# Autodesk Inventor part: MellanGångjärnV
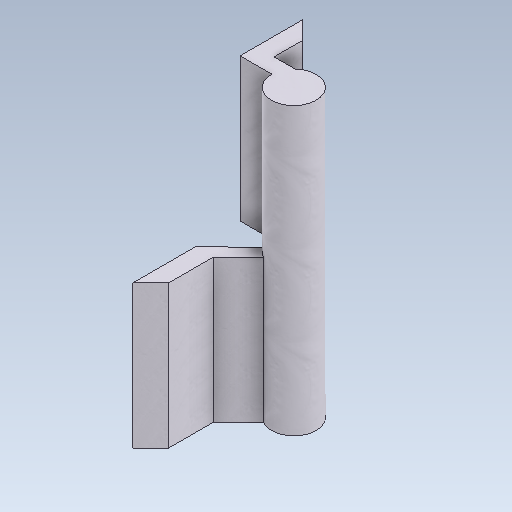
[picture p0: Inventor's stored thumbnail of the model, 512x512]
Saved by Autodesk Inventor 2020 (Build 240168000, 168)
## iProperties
Created: 2019-06
Part Number: MellanGångjärnV
Material: Aluminum 6061, Welded
Document SubType Name: Modeling
Designer: cl
Density: 2.7 g/cm^3
Appearance: Weld - Aluminum
Author: cl
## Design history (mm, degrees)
sketch "Sketch1"
  geometry: L1 (0, 0)-(0, -35); L2 (0, -35)-(-19.282, -53.9); L3 (-24.182, -48.901)-(-10, -35); L4 (-10, -35)-(-10, -10); L5 (-10, -10)-(0, 0); L6 (-19.282, -53.9)-(-24.182, -48.901); A1 r 12.5 centre (-30.302, -59.801) between (-24.182, -48.901) and (-19.282, -53.9)
  constraints: 12 end point, 3 point on circle, 2 parallel, 1 centre point, 1 perpendicular, 1 vertical
  dimensions: "d0" = 35 distance of L1.start L1.end; "d1" = 27 distance of L1.end L2.end; "d3" = 10 distance between parallel lines of L4 L1; "d4" = 135 deg angle of L1 L5; "d5" = 0 vertical distance of L3.end L1.end; "d6" = 25 diameter of A1; "d7" = 7 distance between parallel lines of L2 L3
extrude "Extrusion1" new body sketch "Sketch1" distance "d8" = 80; taper "d9" = 0 deg
sketch "Sketch2"
  geometry: L1 (10, 10)-(10, 35) reference; L2 (10, 35)-(24.182, 48.901) reference; L3 (19.282, 53.9)-(0, 35) reference; L4 (0, 35)-(0, 0) reference; L5 (0, 0)-(10, 10) reference; L6 (0, 60)-(0, 95); L7 (17.803, 60)-(0, 60); L8 (0, 95)-(10, 85); L9 (0, 95)-(14.142, 95); L10 (10, 85)-(10, 69); L11 (10, 69)-(21.839, 69); L12 (0, 35)-(0, 0) reference; A1 r 12.5 centre (30.302, 59.801) between (24.182, 48.901) and (19.282, 53.9) reference; A2 r 12.5 centre (30.302, 59.801) between (24.182, 48.901) and (19.282, 53.9) reference; A3 r 12.5 centre (30.302, 59.801) between (17.803, 60) and (21.839, 69)
  constraints: 12 end point, 4 point on circle, 2 vertical, 1 centre point, 1 coincident, 1 collinear, 1 equal length, 1 horizontal, 1 perpendicular
  dimensions: "d10" = 35 distance of L6.start L6.end; "d11" = 25 distance of L3.end L6.start; "d12" = 45 deg angle of L8 L9; "d13" = 10 distance between parallel lines of L6 L10; "d18" = 9 vertical distance of L11.end L7.start; "d19" = 9 distance from line of L10.end L7
extrude "Extrusion2" join sketch "Sketch2" distance "d20" = 80; taper "d21" = 0 deg
body "Solid1"
node "Projected Loop1"
